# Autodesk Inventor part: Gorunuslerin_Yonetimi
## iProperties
Company: Autodesk, Inc.
Shininess: 64.0
Length Units: 11269
Angle Units: 11279
Time Units: 11290
Mass Units: 11283
Length Display Precision: 3
Angle Display Precision: 2
Compacted: True
Part Number: Gorunuslerin_Yonetimi
Document SubType Name: Modeling
Created: 2003-11
Catalog Web Link: www.autodesk.com
Vendor: Autodesk, Inc.
Designer: Administrator
Manufacturer: Standard
Standards Organization: Custom
Density: 1 g/cm^3
Density: 0.0
Volumn: 0.0
Area: 0.0
PropertySet Name: Model Information
Control State: 0
Master: False
Checked Out: False
Author: Administrator
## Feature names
1. Extrusion1
2. Extrusion2
3. Hole1
4. Extrusion3
5. Hole2
6. Hole3
7. Hole4
8. Hole5
9. Extrusion4
10. Chamfer1
